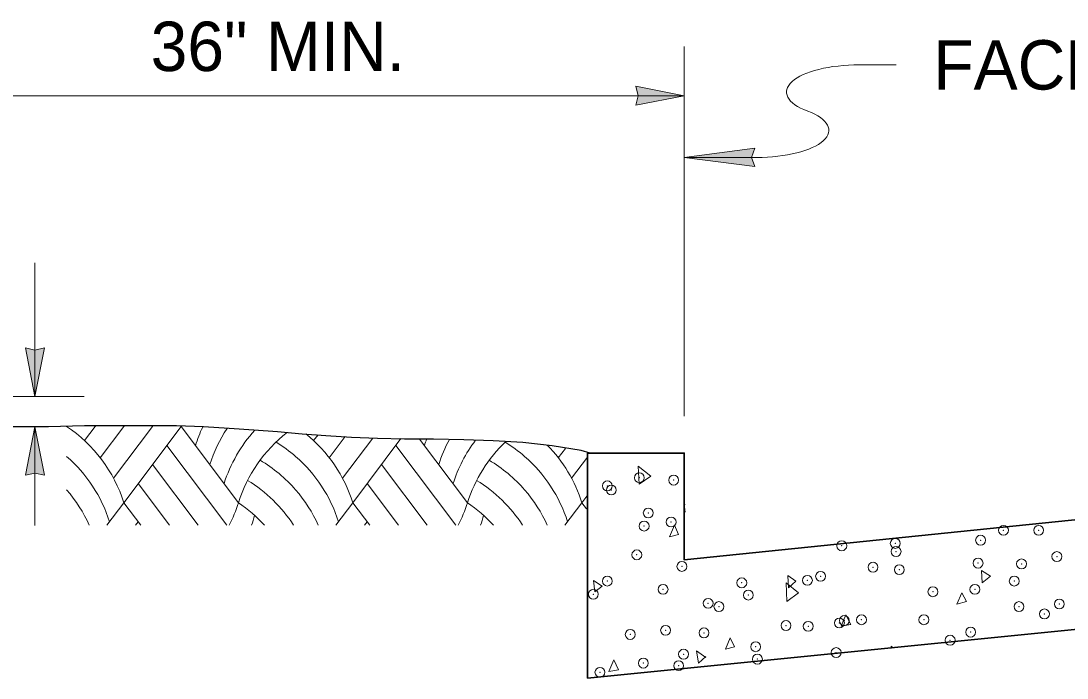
# Model space of a CAD drawing. Extents: x 99860 to 103153, y 99998 to 102077.
# Drawn here: x 100452.7 to 100791.9, y 100711.2 to 100924.1 of the extents above; entities that cross this region are included whole.
import ezdxf
from ezdxf.enums import TextEntityAlignment as Align

# ---------------------------------------------------------------- set-up
doc = ezdxf.new("R2010")
doc.units = 0
doc.header["$LTSCALE"] = 6.4
doc.header["$PDMODE"] = 32
doc.header["$PDSIZE"] = 3.2
for name, color, linetype, lineweight in [('10', 7, 'Continuous', 13), ('14', 7, 'Continuous', 13), ('15', 7, 'Continuous', 13), ('17', 7, 'Continuous', 35), ('20', 7, 'Continuous', 13), ('28', 7, 'Continuous', 13), ('8', 7, 'Continuous', 25)]:
    doc.layers.add(name, color=color, linetype=linetype, lineweight=lineweight)

msp = doc.modelspace()

# ---------------------------------------------------------------- hatches: boundary and pattern name
at = {"layer": '14'}
msp.add_hatch(color=256, dxfattribs=at).paths.add_polyline_path([(100667.807, 100879.872), (100690.636, 100876.887), (100689.58, 100879.872), (100690.637, 100882.857)])
at = {"layer": '15'}
for points in [[(100667.807, 100899.872), (100652.082, 100896.788), (100652.81, 100899.872), (100652.082, 100902.956)], [(100457.282, 100802.397), (100460.366, 100818.122), (100457.282, 100817.394), (100454.198, 100818.122)], [(100457.282, 100792.597), (100460.366, 100776.872), (100457.282, 100777.6), (100454.198, 100776.872)]]:
    msp.add_hatch(color=256, dxfattribs=at).paths.add_polyline_path(points)

# ---------------------------------------------------------------- linework, layer by layer
at = {"layer": '10'}
for p, q in [((100653.22, 100773.947), (100652.907, 100779.835)), ((100656.92, 100776.622), (100652.907, 100779.835)), ((100653.22, 100773.947), (100656.92, 100776.622)), ((100668.107, 100764.935), (100667.807, 100767.56)), ((100668.107, 100767.31), (100667.807, 100767.56)), ((100663.057, 100756.922), (100664.632, 100760.685)), ((100665.982, 100757.722), (100664.632, 100760.685)), ((100663.057, 100756.922), (100665.982, 100757.722)), ((100764.382, 100742.022), (100764.132, 100746.035)), ((100767.032, 100744.147), (100764.132, 100746.035)), ((100638.845, 100739.122), (100638.32, 100742.822)), ((100641.22, 100740.947), (100638.32, 100742.822)), ((100701.595, 100740.447), (100701.357, 100744.435)), ((100703.97, 100742.585), (100701.357, 100744.435)), ((100701.595, 100740.447), (100703.97, 100742.585)), ((100764.382, 100742.022), (100767.032, 100744.147)), ((100638.845, 100739.122), (100641.22, 100740.947)), ((100701.07, 100735.922), (100700.795, 100742.022)), ((100704.807, 100738.822), (100700.795, 100742.022)), ((100701.07, 100735.922), (100704.807, 100738.822)), ((100756.12, 100735.147), (100757.757, 100738.822)), ((100759.295, 100735.922), (100757.757, 100738.822)), ((100756.12, 100735.147), (100759.295, 100735.922)), ((100718.62, 100727.935), (100720.22, 100731.66)), ((100721.832, 100728.485), (100720.22, 100731.66)), ((100718.62, 100727.935), (100721.832, 100728.485)), ((100681.157, 100720.497), (100682.695, 100724.235)), ((100684.057, 100721.31), (100682.695, 100724.235)), ((100672.37, 100715.997), (100671.807, 100719.972)), ((100674.77, 100717.847), (100671.807, 100719.972)), ((100681.157, 100720.497), (100684.057, 100721.31)), ((100734.845, 100720.747), (100734.845, 100721.547)), ((100735.645, 100721.022), (100734.845, 100721.547)), ((100643.345, 100713.285), (100644.982, 100717.047)), ((100646.532, 100713.872), (100644.982, 100717.047)), ((100672.37, 100715.997), (100674.77, 100718.122)), ((100643.345, 100713.285), (100646.532, 100713.872))]:
    msp.add_line(p, q, dxfattribs=at)
for p in [(100653.22, 100776.072), (100664.382, 100775.297), (100642.857, 100773.447), (100644.157, 100772.097), (100656.12, 100764.66), (100663.545, 100761.735), (100654.795, 100760.41), (100771.295, 100759.047), (100782.695, 100759.047), (100736.195, 100754.797), (100763.857, 100755.835), (100652.42, 100751.097), (100718.87, 100754.022), (100736.47, 100752.172), (100763.057, 100748.41), (100777.145, 100748.16), (100788.595, 100750.535), (100667.032, 100747.335), (100711.995, 100744.147), (100729.007, 100747.085), (100737.52, 100746.285), (100642.857, 100742.585), (100686.457, 100742.022), (100707.732, 100742.822), (100774.77, 100742.585), (100638.32, 100738.322), (100660.932, 100739.897), (100688.582, 100738.047), (100748.407, 100739.122), (100762.007, 100739.897), (100675.545, 100735.397), (100679.032, 100734.322), (100776.32, 100734.322), (100789.395, 100735.147), (100784.582, 100731.947), (100700.795, 100728.185), (100707.982, 100727.935), (100718.095, 100729.01), (100719.695, 100729.81), (100725.257, 100730.06), (100745.482, 100730.06), (100650.282, 100725.285), (100661.732, 100726.635), (100674.182, 100725.81), (100760.657, 100726.047), (100690.957, 100721.31), (100753.995, 100723.435), (100667.557, 100718.897), (100691.52, 100717.297), (100717.045, 100719.422), (100654.545, 100715.997), (100665.982, 100715.172), (100640.457, 100713.035)]:
    msp.add_point(p, dxfattribs=at)
at = {"layer": '14'}
for p, q in [((100724.543, 100909.872), (100736.543, 100909.872)), ((100667.807, 100879.872), (100691.238, 100879.872))]:
    msp.add_line(p, q, dxfattribs=at)
msp.add_lwpolyline([(100667.807, 100879.872), (100690.636, 100876.887), (100689.58, 100879.872), (100690.637, 100882.857)], close=True, dxfattribs=at)
for centre, start_param, end_param in [((100724.375, 100901.086), 4.7052439, 7.0686238), ((100691.238, 100888.659), 1.5707963, 3.926959)]:
    msp.add_ellipse(centre, major_axis=(-23.431, 0), ratio=0.375, start_param=start_param, end_param=end_param, dxfattribs=at)
at = {"layer": '15'}
for p, q in [((100667.807, 100796.085), (100667.807, 100915.872)), ((100667.807, 100899.872), (100404.282, 100899.872)), ((100457.282, 100802.397), (100457.282, 100845.725)), ((100433.01, 100802.397), (100473.282, 100802.397)), ((100457.282, 100760.597), (100457.282, 100792.597))]:
    msp.add_line(p, q, dxfattribs=at)
for points in [[(100667.807, 100899.872), (100652.082, 100896.788), (100652.81, 100899.872), (100652.082, 100902.956)], [(100457.282, 100802.397), (100460.366, 100818.122), (100457.282, 100817.394), (100454.198, 100818.122)], [(100457.282, 100792.597), (100460.366, 100776.872), (100457.282, 100777.6), (100454.198, 100776.872)]]:
    msp.add_lwpolyline(points, close=True, dxfattribs=at)
at = {"layer": '17'}
msp.add_lwpolyline([(100808.232, 100727.935), (100799.72, 100727.41), (100636.47, 100711.16), (100636.47, 100784.085), (100667.807, 100784.085), (100667.807, 100749.46), (100797.595, 100762.81), (100797.907, 100762.81)], dxfattribs=at)
at = {"layer": '28'}
for p, q in [((100473.381, 100788.105), (100476.844, 100792.722)), ((100476.844, 100792.722), (100476.897, 100792.793)), ((100478.477, 100782.526), (100486.125, 100792.722)), ((100482.782, 100775.89), (100495.405, 100792.722)), ((100486.125, 100792.722), (100486.21, 100792.836)), ((100486.125, 100767.973), (100504.686, 100792.722)), ((100495.405, 100792.722), (100495.454, 100792.787)), ((100504.675, 100792.738), (100504.686, 100792.722)), ((100504.686, 100792.722), (100523.248, 100767.973)), ((100547.626, 100788.105), (100549.067, 100790.027)), ((100500.046, 100786.535), (100519.453, 100760.658)), ((100552.722, 100782.526), (100557.885, 100789.409)), ((100557.027, 100775.89), (100566.799, 100788.92)), ((100560.37, 100767.973), (100575.947, 100788.743)), ((100574.291, 100786.535), (100593.698, 100760.658)), ((100582.004, 100788.625), (100597.493, 100767.973)), ((100626.967, 100782.526), (100629.257, 100785.579)), ((100495.405, 100780.348), (100510.172, 100760.658)), ((100569.65, 100780.348), (100584.417, 100760.658)), ((100631.272, 100775.89), (100636.445, 100782.789)), ((100490.765, 100774.161), (100500.892, 100760.658)), ((100565.01, 100774.161), (100575.137, 100760.658)), ((100634.615, 100767.973), (100636.205, 100770.094)), ((100480.638, 100760.658), (100486.125, 100767.973)), ((100486.125, 100767.973), (100491.611, 100760.658)), ((100554.883, 100760.658), (100560.37, 100767.973)), ((100560.37, 100767.973), (100565.856, 100760.658)), ((100489.919, 100760.658), (100490.765, 100761.786)), ((100564.164, 100760.658), (100565.01, 100761.786))]:
    msp.add_line(p, q, dxfattribs=at)
msp.add_lwpolyline([(100629.128, 100760.658), (100634.615, 100767.973), (100636.127, 100765.957)], dxfattribs=at)
for centre, start, end in [((100441.362, 100753.737), 56.0955, 56.09634), ((100441.362, 100753.737), 17.6434, 56.0955), ((100549.448, 100778.485), 162.33694, 162.3566), ((100554.089, 100772.298), 154.54467, 162.3566), ((100558.729, 100766.111), 146.50407, 162.3566), ((100563.37, 100759.924), 137.82305, 162.3566), ((100568.01, 100753.737), 128.04764, 162.3566), ((100515.607, 100753.737), 17.6434, 51.12509), ((100510.968, 100747.55), 48.95968, 58.54646), ((100628.334, 100772.298), 159.71772, 162.3566), ((100632.974, 100766.111), 151.62004, 162.3566), ((100637.615, 100759.924), 142.93937, 162.3566), ((100642.255, 100753.737), 133.47034, 162.3566), ((100585.213, 100747.55), 48.95968, 58.54646), ((100589.852, 100753.737), 17.6434, 44.46458), ((100436.722, 100747.55), 17.6434, 48.95882), ((100510.967, 100747.55), 17.6434, 48.95974), ((100585.212, 100747.55), 17.6434, 48.95974), ((100506.328, 100741.362), 40.94134, 59.30215), ((100580.573, 100741.362), 40.94134, 59.30215), ((100501.687, 100735.175), 32.85565, 58.48736), ((100575.932, 100735.175), 32.85565, 58.48736), ((100432.082, 100741.362), 24.2553, 40.94034), ((100506.327, 100741.362), 24.25529, 40.94141), ((100580.572, 100741.362), 24.25529, 40.94141), ((100478.485, 100782.21), 332.6888, 342.3566), ((100497.047, 100728.988), 42.39561, 56.09639), ((100552.73, 100782.21), 332.6888, 342.3566), ((100571.292, 100728.988), 42.39561, 56.09639), ((100483.126, 100776.023), 340.90703, 345.01126), ((100557.371, 100776.023), 340.90703, 345.01126)]:
    msp.add_arc(centre, 46.972, start, end, dxfattribs=at)
at = {"layer": '8'}
msp.add_lwpolyline([(100637.245, 100784.085), (100634.345, 100784.86), (100625.007, 100786.46), (100615.445, 100787.51), (100605.857, 100788.06), (100596.295, 100788.347), (100586.457, 100788.585), (100577.145, 100788.585), (100568.382, 100788.835), (100559.882, 100789.11), (100551.607, 100789.635), (100543.907, 100790.197), (100535.882, 100790.96), (100528.207, 100791.522), (100520.22, 100792.01), (100511.982, 100792.597), (100503.195, 100792.847), (100493.92, 100792.847), (100484.045, 100792.847), (100473.407, 100792.847), (100461.72, 100792.597), (100448.957, 100792.597)], dxfattribs=at)

# ---------------------------------------------------------------- texts
at = {"layer": '20'}
msp.add_text('36" MIN.', height=16, dxfattribs=at).set_placement((100536.048, 100907.872), align=Align.CENTER)
msp.add_text('FACE OF CURB', height=16, dxfattribs=at).set_placement((100748.543, 100901.872))

doc.saveas('drawing.dxf')
